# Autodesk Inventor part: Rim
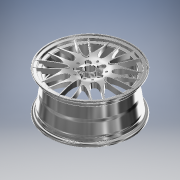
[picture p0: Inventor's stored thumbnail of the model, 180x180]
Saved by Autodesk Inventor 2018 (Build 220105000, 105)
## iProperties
Shininess: 64.0
Length Units: 11269
Angle Units: 11279
Time Units: 11290
Mass Units: 11283
Length Display Precision: 3
Angle Display Precision: 2
Compacted: True
Part Number: Rim
Document SubType Name: Modeling
Created: 2003-06
Manufacturer: Standard
Standards Organization: Custom
Density: 2.71 g/cm^3
Material: Aluminum-6061
Mass: 9948.11 g
Surface Area: 8992.46 cm^2
Volume: 3670.89 cm^3
Appearance: Chrome - Polished
Density: 0.0
Volumn: 0.0
Area: 0.0
PropertySet Name: Model Information
Control State: 0
Master: False
Checked Out: False
Author: Autodesk, Inc.
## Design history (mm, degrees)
workplane "Work Plane4"
workplane "Work Plane1"
sketch "Spoke Side"
  geometry: L1 (0, -11162.344)-(0, 13420.953) reference; L2 (-1298.767, 0)-(7792.602, 0) reference; L3 (0, 55)-(10.286, 55); L4 (205.698, 37.987)-(254.302, 42.013); L5 (37.4, 37.385)-(62.6, 42.615); L6 (0, 0)-(60, 0); L7 (60, 0)-(60, 5); L8 (60, 5)-(65.959, 10); L9 (62.17, 6.821)-(69.748, 13.179); L10 (222.425, 21.138)-(237.575, 18.862); L11 (230, 40)-(230, 20); L12 (0, 55)-(0, 0); A1 r 209.241 centre (212.724, 248.526) between (210.568, 39.297) and (249.283, 42.504); A2 r 109.305 centre (27.793, 147.025) between (39.866, 38.389) and (59.938, 42.554); A3 r 90.833 centre (0, -35.833) between (50, 40) and (0, 55); A4 r 10000 centre (6493.835, -7650.444) between (68.99, 12.543) and (68.985, 12.55); A5 r 10000 centre (1715.468, 9909.054) between (223.941, 20.912) and (236.06, 19.092); 2 further points
  constraints: 20 end point, 8 midpoint, 6 point on circle, 5 centre point, 2 collinear, 2 parallel, 2 point on line, 1 perpendicular, 1 tangent, 14 other
  dimensions: "d1" = 55 distance between parallel lines of L2 L3; "d3" = 460 diameter of L11.start L1; "d4" = 40 distance from line of L2 L11.start; "d5" = 100 diameter of A3.start L1; "d6" = 50 distance from line of L2 point (110.655, 50); "d7" = 40 distance from line of L2 A3.start; "d8" = 60 distance of L6.start L6.end; "d9" = 0 distance between parallel lines of L2 L6; "d10" = 5 distance of L6.end L7.end; "d11" = 460 diameter of L11.end L1 (= d3); "d12" = 130 deg angle of L7 L8; "d13" = 5 vertical distance of L7.end L8.end; "d14" = 20 distance of L11.start L11.end
revolve "Revolution1" stored, may be unused: angle "d15" = 90 deg
sketch "Spoke Top"
  geometry: L1 (0, 35.567)-(0, -35.567) reference; L2 (-329.417, 0)-(-41.965, 0) reference; A1 r 22.668 centre (-265.684, 0) between (-282.023, 15.713) and (-282.023, -15.713); 5 further points
  constraints: 3 symmetric about line, 2 point on circle, 1 centre point, 1 point on line, 7 other
  dimensions: "d137" = 85 distance from line of L1 point (-85, 0); "d138" = 30 distance of point (-95.703, -15) point (-95.703, 15); "d139" = 40 distance of point (-231.71, -20) point (-231.71, 20)
extrude "Extrusion9" cut sketch "Spoke Top" extent not by distance; stored distance "d141" = 10; taper "d142" = -5 deg
pattern_circular "Circular Pattern6" dims angle "d145" = 360 deg
sketch "Sketch19"
  geometry: L1 (-50, 0)-(-86.059, 0) reference; L2 (-437.715, 0)-(341.286, 0) reference; L3 (0, 398.906)-(0, -364.894) reference; L4 (0, 0)-(-268.128, 194.806) reference; L5 (-101.443, 282.759)-(-96.692, 201.808); L6 (-221.81, 29.598)-(-300.268, 9.1); A1 r 230 centre (0, 0) between (196.304, -119.853) and (196.304, 119.853) reference; A2 r 230 centre (0, 0) between (174.648, 149.66) and (-53.325, 223.733) reference; A3 r 230 centre (0, 0) between (-88.366, 212.348) and (-229.261, 18.422) reference; A4 r 230 centre (0, 0) between (-229.261, -18.422) and (-88.366, -212.348) reference; A5 r 230 centre (0, 0) between (-53.325, -223.733) and (174.648, -149.66) reference; A6 r 130.796 centre (31.504, 249.946) between (-95.482, 281.288) and (-90.944, 203.966); A7 r 130.796 centre (-227.977, -107.2) between (-222.087, 23.464) and (-297.026, 3.886); A8 r 157.848 centre (-117.742, 85.544) between (-99.068, 242.284) and (-261.039, 19.349); 10 further points
  constraints: 6 end point, 4 midpoint, 4 point on circle, 3 centre point, 3 symmetric about line, 1 horizontal alignment, 1 point on line, 13 other
  dimensions: "d147" = 100 distance of A1.centre point (-80.902, 58.779); "d148" = 10 dimension on L6.start L6.end (= d149); "d149" = 10 dimension on L5.start L5.end
extrude "Extrusion10" cut sketch "Sketch19" extent not by distance; stored distance "d150" = 10; taper "d151" = -5 deg
pattern_circular "Circular Pattern7" dims angle "d154" = 360 deg
sketch "Sketch20"
  geometry: L1 (-300.487, 0)-(50.081, 0) reference; L2 (0, 230.697)-(0, -38.449) reference; L3 (0, 0)-(-250.021, 181.651) reference; L4 (-230.266, 187.463)-(-204.629, 181.002); L5 (-235.377, 138.681)-(-249.444, 161.066); A1 r 50.044 centre (-229.678, 135.707) between (-205.46, 179.5) and (-230.246, 185.747); A2 r 50.044 centre (-200.039, 176.501) between (-247.806, 161.578) and (-234.205, 139.935); A3 r 27.755 centre (-215.47, 156.548) between (-217.447, 184.233) and (-242.411, 149.874); 5 further points
  constraints: 6 end point, 4 midpoint, 4 point on circle, 3 centre point, 3 point on line, 3 symmetric about line, 13 other
  dimensions: "d157" = 80 distance of L3.start point (-64.721, 47.023); "d158" = 285 distance of L3.start A3.start; "d159" = 5 dimension on L4.start L4.end; "d160" = 5 dimension on L5.start L5.end (= d159); "d161" = 22 distance of point (-76.988, 42.339) point (-64.057, 60.137)
extrude "Extrusion12" join sketch "Sketch20" distance "d164" = 40; taper "d165" = 5 deg
sketch "Sketch21" dims "d166" = 5
  geometry: L1 (0, 0)-(-271.586, 197.319); A1 r 27.755 centre (-215.47, 156.548) between (-217.447, 184.233) and (-242.411, 149.874) reference; 3 further points
  constraints: 2 end point, 2 point on line, 7 other
extrude "Extrusion13" cut sketch "Sketch21" extent not by distance; stored distance "d167" = 20; taper "d168" = -1 deg
pattern_circular "Circular Pattern8" dims angle "d171" = 360 deg
sketch "Sketch22"
  geometry: L1 (60, 0)-(60, 5) reference; L2 (60, 5)-(65.959, 10) reference; L3 (60, 0)-(60, -25.42); L4 (60, -25.42)-(230, -25.42); L5 (230, -25.42)-(230, 20); L6 (0, 55)-(0, 0) reference
  constraints: 6 end point, 1 collinear, 1 parallel, 1 perpendicular
revolve "Revolution3" sketch "Sketch22" stored, may be unused: angle "d172" = 90 deg
sketch "Sketch23"
  geometry: C1 r 225 at (0, 0); C2 r 325 at (0, 0); 1 further point
  constraints: 2 centre point, 2 coincident
  dimensions: "d173" = 450 diameter of C1; "d174" = 650 diameter of C2
extrude "Extrusion14" cut sketch "Sketch23" extent not by distance; stored distance "d175" = 20; taper "d176" = 0 deg
workplane "Work Plane5"
sketch "Sketch24"
  geometry: L1 (0, 202.622)-(0, -33.77) reference; L2 (-278.885, 0)-(46.481, 0) reference; L3 (0, 0)-(-232.404, 168.851) reference; C1 r 12.5 at (-36.406, 26.45); 4 further points
  constraints: 5 point on line, 2 end point, 1 centre point, 1 symmetric about line, 5 other
  dimensions: "d179" = 25 diameter of C1; "d180" = 45 distance of L3.start C1.centre; "d181" = 28 distance of L3.start point (-22.652, 16.458); "d182" = 70 distance of L3.start point (-56.631, 41.145); "d183" = 32 distance of point (-47.788, 14.943) point (-28.979, 40.832)
extrude "Extrusion15" cut sketch "Sketch24" distance "d184" = 40; taper "d185" = -3 deg
sketch "Sketch25"
  geometry: L1 (0, 318.17)-(0, -318.17) reference; L2 (-321.394, 0)-(321.205, 0) reference; L3 (0, 0)-(-199.929, 145.257); 2 further points
  constraints: 2 end point, 2 point on line, 1 midpoint
  dimensions: "d186" = 36 deg angle of L2 L3; "d187" = 45 distance of L3.start point (-36.406, 26.45)
hole "Hole2" sketch "Sketch25" at (-36.406, 26.45) diameter "d188" = 12; stored, may be unused: countersink angle "d192" = 82 deg, drill point angle "d194" = 118 deg; dims "d189" = 6, "d190" = 4, "d191" = 2, "d193" = 8
sketch "Sketch26"
  geometry: L1 (0, 10.5)-(0, -10.5) reference; L2 (-87, 0)-(14.5, 0) reference; C1 r 7.5 at (-65, 0); 1 further point
  constraints: 1 centre point, 1 point on line
  dimensions: "d195" = 65 distance from line of L1 C1.centre; "d196" = 15 diameter of C1
extrude "Extrusion16" cut sketch "Sketch26" distance "d197" = 40; taper "d198" = -3 deg
pattern_circular "Circular Pattern9" dims angle "d201" = 360 deg
sketch "Sketch27"
  geometry: C1 r 25 at (0, 0); 1 further point
  constraints: 1 centre point, 1 coincident
  dimensions: "d202" = 50 diameter of C1
extrude "Extrusion17" cut sketch "Sketch27" extent not by distance; stored distance "d203" = 30; taper "d204" = -5 deg
chamfer "Chamfer3" distance "d205" = 2; stored, may be unused: second distance "d206" = 2, angle "d245" = 45 deg
fillet "Fillet9" dims "d210" = 5
fillet "Fillet10" dims "d211" = 2
fillet "Fillet11" dims "d212" = 1
fillet "Fillet12" dims "d244" = 5
sketch "Rim"
  geometry: L1 (0, -207.58)-(0, 101.58) reference; L2 (205.287, 15.102)-(198.66, 13.583); L3 (191.484, -47.284)-(187.573, 24.419); L4 (194.009, 7.408)-(197.061, -48.544); L5 (210.521, -135.213)-(211.543, -143.716); L6 (207.002, -147.832)-(197.328, -67.37); L7 (211.5, 28.893)-(211.5, 22.9); L8 (212.232, 37.523)-(211.523, 29.416); L9 (221, 43)-(218.209, 43); L10 (223, 52)-(223, 55); L11 (230, 55)-(230, 52); L12 (225, 57)-(228, 57); L13 (198.023, -53.072)-(200.538, -59.666); L14 (195.866, -61.447)-(192.767, -53.321); L15 (202.292, -66.774)-(208.594, -119.191); L16 (217.5, -149)-(221, -149); L17 (221, -156)-(215, -156); L18 (224, -161)-(224, -159); L19 (230, -158)-(230, -161); L20 (228, -163)-(226, -163); L21 (221, 50)-(209, 50); L22 (197, 37)-(192, 37); L23 (-722.944, 0)-(390.999, 0) reference; L24 (197, 37)-(205, 37); L25 (207, 39)-(207, 48); A1 r 752.499 centre (-563.809, -16.57) between (187.573, 24.419) and (187.133, 31.809); A2 r 8 centre (203.5, 22.9) between (205.287, 15.102) and (211.5, 22.9); A3 r 6 centre (200, 7.734) between (198.66, 13.583) and (194.009, 7.408); A4 r 6 centre (217.5, -143) between (211.543, -143.716) and (217.5, -149); A5 r 13.486 centre (223.91, -133.603) between (210.863, -130.19) and (210.521, -135.213); A6 r 9.5 centre (201.672, -127.786) between (210.863, -130.19) and (210.019, -123.25); A7 r 13.492 centre (221.874, -116.809) between (208.594, -119.191) and (210.019, -123.25); A8 r 6 centre (217.5, 28.893) between (211.523, 29.416) and (211.5, 28.893); A9 r 6 centre (218.209, 37) between (218.209, 43) and (212.232, 37.523); A10 r 2 centre (221, 52) between (221, 50) and (223, 52); A11 r 9 centre (221, 52) between (221, 43) and (230, 52); A12 r 2 centre (225, 55) between (225, 57) and (223, 55); A13 r 2 centre (228, 55) between (230, 55) and (228, 57); A14 r 15 centre (212.039, -47.727) between (197.061, -48.544) and (198.023, -53.072); A15 r 20 centre (211.455, -46.195) between (191.484, -47.284) and (192.767, -53.321); A16 r 30 centre (172.507, -70.355) between (202.292, -66.774) and (200.538, -59.666); A17 r 25 centre (172.507, -70.355) between (197.328, -67.37) and (195.866, -61.447); A18 r 8 centre (215, -148) between (207.002, -147.832) and (215, -156); A19 r 9 centre (221, -158) between (230, -158) and (221, -149); A20 r 3 centre (221, -159) between (224, -159) and (221, -156); A21 r 2 centre (226, -161) between (224, -161) and (226, -163); A22 r 2 centre (228, -161) between (228, -163) and (230, -161); A23 r 2 centre (209, 48) between (209, 50) and (207, 48); A24 r 4.877 centre (192, 32.123) between (192, 37) and (187.133, 31.809); A25 r 2 centre (205, 39) between (205, 37) and (207, 39); 4 further points
  constraints: 50 point on circle, 46 end point, 45 tangent, 25 centre point, 3 parallel, 1 perpendicular
  dimensions: "d266" = 2 radius of A23; "d267" = 220 distance between parallel lines of L20 L12; "d268" = 7 distance between parallel lines of L17 L16; "d269" = 5 distance between parallel lines of L6 L5; "d270" = 5 distance between parallel lines of L6 L15; "d271" = 5 distance between parallel lines of L14 L13; "d272" = 5.5 distance between parallel lines of L3 L4; "d273" = 50 distance between parallel lines of L23 L21; "d274" = 7 distance between parallel lines of L9 L21; "d276" = 8 radius of A2; "d277" = 9 radius of A11; "d278" = 2 radius of A13; "d279" = 2 radius of A12; "d280" = 2 radius of A10; "d282" = 6 radius of A3; "d283" = 15 radius of A14; "d284" = 20 radius of A15; "d285" = 30 radius of A16; "d286" = 25 radius of A17; "d287" = 9.5 radius of A6; "d288" = 6 radius of A4; "d289" = 9 radius of A19; "d290" = 2 radius of A22; "d291" = 2 radius of A21; "d292" = 3 radius of A20; "d293" = 8 radius of A18; "d294" = 57 distance between parallel lines of L23 L12; "d295" = 7 distance between parallel lines of L20 L17; "d296" = 460 diameter of L11 L1; "d298" = 460 diameter of L19 L1; "d299" = 18.5 distance between parallel lines of L7 L11; "d300" = 9 distance from line of A11.centre L11 (derived); "d301" = 21 distance from line of L11 A23.centre; "d304" = 38 distance from line of L11 A24.centre; "d305" = 30 distance from line of L11 A3.centre; "d306" = 7 distance between parallel lines of L11 L10; "d307" = 6 distance between parallel lines of L18 L19; "d308" = 9 distance from line of A19.centre L19 (derived); "d309" = 12.5 distance from line of A4.centre L19; "d310" = 15 distance from line of A18.centre L19; "d311" = 46.19501 distance from line of L23 A15.centre; "d312" = 47.72741 distance from line of L23 A14.centre; "d313" = 70.3547 distance from line of L23 A17.centre; "d314" = 77.49796 distance from line of L23 point (212.258, -77.498); "d332" = 20 distance between parallel lines of L12 L22; "d333" = 2 radius of A25
revolve "Revolution4" stored, may be unused: angle "d214" = 90 deg
sketch "Sketch33"
  geometry: L1 (208, 21)-(211, 21) reference; L2 (199, 8.5)-(199, 12) reference; L3 (185.213, 1.521)-(193.716, 2.543) reference; L4 (116.774, -6.708)-(169.191, -0.406) reference; L5 (103.072, -10.977)-(109.666, -8.462) reference; L6 (42.592, -14.991)-(98.544, -11.939) reference; L7 (34.898, -3.713)-(36.417, -10.34) reference; L8 (21.107, 2.5)-(27.1, 2.5) reference; L9 (12.477, 3.232)-(20.584, 2.523) reference; L10 (7, 12)-(7, 9.209) reference; L11 (-5, 21)-(-2, 21) reference; L12 (258.433, -209)-(-59.6, -209) reference; A1 r 9 centre (208, 12) between (208, 21) and (199, 12) reference; A2 r 6 centre (193, 8.5) between (193.716, 2.543) and (199, 8.5) reference; A3 r 13.486 centre (183.603, 14.91) between (180.19, 1.863) and (185.213, 1.521) reference; A4 r 9.5 centre (177.786, -7.328) between (180.19, 1.863) and (173.25, 1.019) reference; A5 r 13.492 centre (166.809, 12.874) between (169.191, -0.406) and (173.25, 1.019) reference; A6 r 30 centre (120.355, -36.493) between (116.774, -6.708) and (109.666, -8.462) reference; A7 r 15 centre (97.727, 3.039) between (98.544, -11.939) and (103.072, -10.977) reference; A8 r 6 centre (42.266, -9) between (36.417, -10.34) and (42.592, -14.991) reference; A9 r 8 centre (27.1, -5.5) between (34.898, -3.713) and (27.1, 2.5) reference; A10 r 6 centre (21.107, 8.5) between (20.584, 2.523) and (21.107, 2.5) reference; A11 r 6 centre (13, 9.209) between (7, 9.209) and (12.477, 3.232) reference; A12 r 9 centre (-2, 12) between (7, 12) and (-2, 21) reference
feature "RevolutionSrf1" sketch "Sketch33" dims angle "d315" = 90 deg
split "Split1"
pattern_circular "Circular Pattern11" dims angle "d317" = 360 deg
sketch "Sketch34"
  geometry: L1 (0, -399.846)-(0, 399.138) reference; L2 (-404.857, 0)-(355.966, 0) reference; L3 (0, 0)-(28.191, 10.261); L4 (0, 0)-(28.191, -10.261); L5 (28.191, 10.261)-(49.334, 17.956); L6 (28.191, -10.261)-(49.334, -17.956); C1 r 60 at (0, 0) reference; A1 r 52.5 centre (0, 0) between (49.334, 17.956) and (49.334, -17.956); A2 r 30 centre (0, 0) between (28.191, -10.261) and (28.191, 10.261); A3 r 52.5 centre (0, 0) between (52.5, 0) and (49.334, 17.956); A4 r 52.5 centre (0, 0) between (49.334, -17.956) and (52.5, 0); A5 r 30 centre (0, 0) between (0, -30) and (28.191, -10.261); A6 r 30 centre (0, 0) between (28.191, 10.261) and (0, -30)
  constraints: 12 point on circle, 8 end point, 6 centre point, 3 coincident, 3 point on line
  dimensions: "d319" = 40 deg angle of L4 L3; "d320" = 20 deg angle of L2 L3 (derived); "d321" = 105 diameter of A1; "d322" = 60 diameter of A2
extrude "Extrusion19" cut sketch "Sketch34" distance "d323" = 15; taper "d324" = -3 deg
fillet "Fillet18" dims "d325" = 2
chamfer "Chamfer5" distance "d326" = 2; stored, may be unused: second distance "d327" = 2, angle "d328" = 45 deg
pattern_circular "Circular Pattern12" dims angle "d330" = 360 deg
fillet "Fillet19" dims "d334" = 2
body "Solid1"
node "Projected Loop2"
body "Srf1"
other parameters: "d155" = 52
